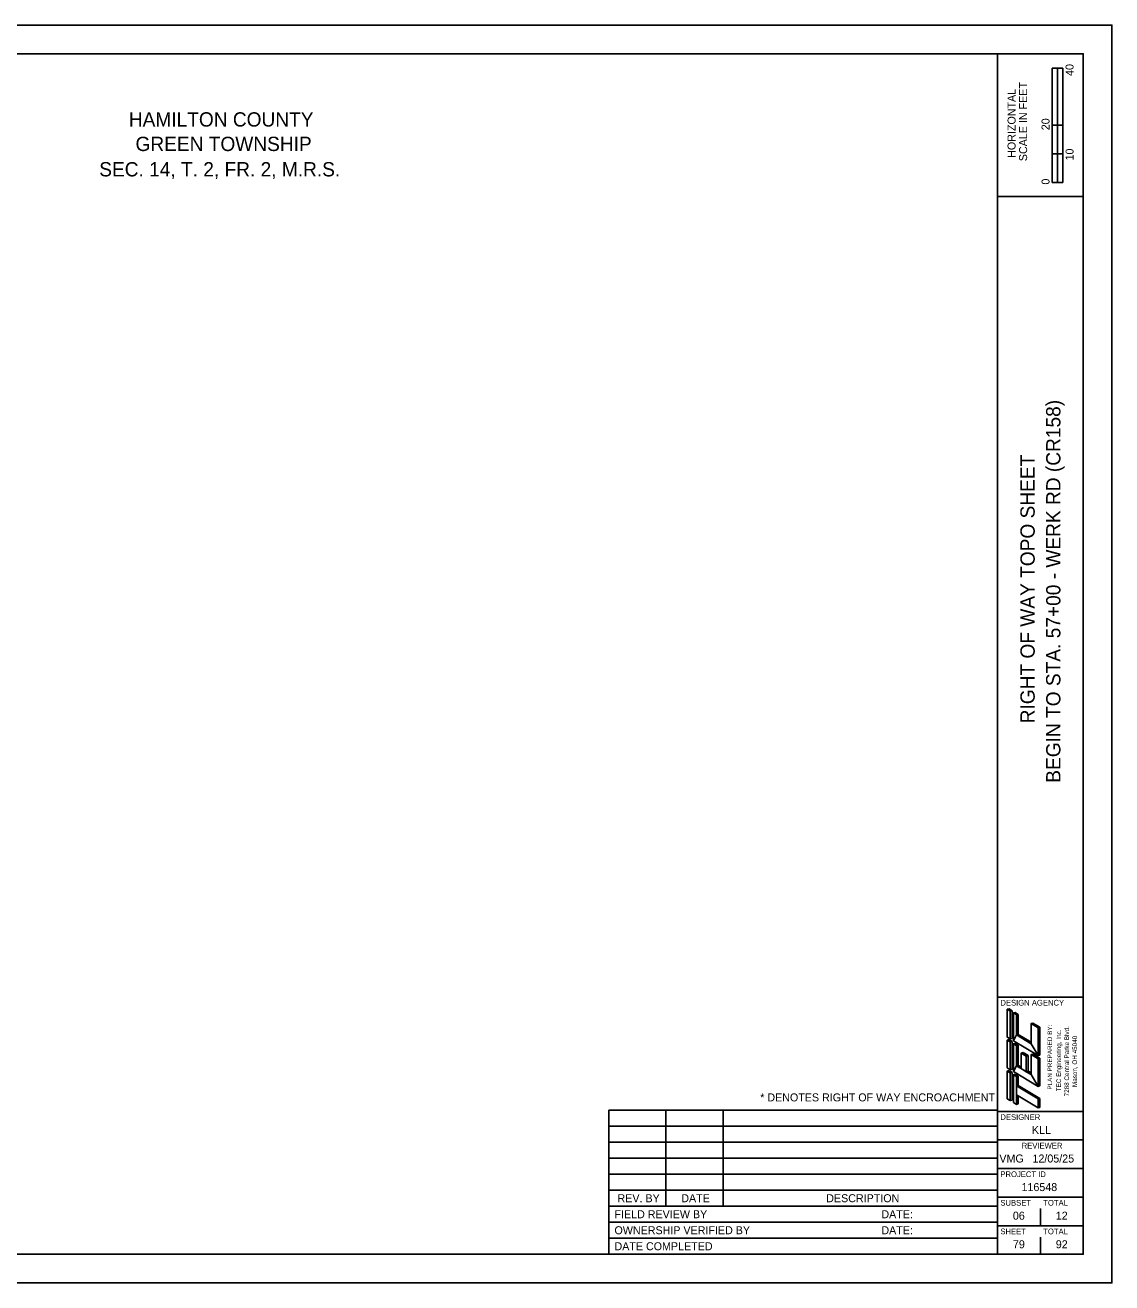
# Model space of a CAD drawing. Extents: x -4 to 34, y 0 to 23.7.
# Drawn here: x 14.98 to 34, y 0 to 22 of the extents above; entities that cross this region are included whole.
import ezdxf

# ---------------------------------------------------------------- set-up
doc = ezdxf.new("R2010")
doc.units = 0
for name, color, linetype in [('_CIVIL_CONSTRUCTION', 7, 'Continuous'), ('Default', 7, 'Continuous'), ('SC_Scratch1', 7, 'Continuous'), ('SG_P_Controllers', 7, 'Continuous'), ('SG_P_Detection', 7, 'Continuous'), ('SG_P_Heads', 7, 'Continuous')]:
    doc.layers.add(name, color=color, linetype=linetype)

msp = doc.modelspace()

# ---------------------------------------------------------------- linework, layer by layer
at = {"layer": '_CIVIL_CONSTRUCTION'}
for p, q in [((32.957, 19.25), (32.957, 21.25)), ((33.144, 21.25), (32.957, 21.25)), ((32.957, 20.25), (32.957, 21.25)), ((32.957, 21.25), (33.05, 21.25)), ((33.05, 21.25), (33.051, 21.25)), ((33.051, 21.25), (33.051, 20.25)), ((33.144, 21.25), (33.144, 19.25)), ((33.051, 20.25), (32.957, 20.25)), ((33.143, 20.25), (33.05, 20.25)), ((33.05, 20.25), (33.05, 19.75)), ((33.143, 19.75), (33.143, 20.25)), ((33.05, 19.75), (32.957, 19.75)), ((32.957, 19.75), (32.957, 19.25)), ((33.05, 19.25), (33.05, 19.75)), ((33.05, 19.75), (33.143, 19.75)), ((33.144, 19.25), (32.957, 19.25)), ((32.957, 19.25), (33.05, 19.25)), ((32.75, 4), (32.75, 4)), ((32.75, 1), (32.75, 1.3)), ((32.375, 0.675), (32.375, 0.675)), ((32.75, 0.5), (32.75, 0.8))]:
    msp.add_line(p, q, dxfattribs=at)
at = {"layer": 'SC_Scratch1'}
for p, q in [((32.169, 4.785), (32.201, 4.794)), ((32.169, 4.299), (32.169, 4.785)), ((32.223, 4.753), (32.169, 4.785)), ((32.255, 4.761), (32.201, 4.794)), ((32.223, 4.753), (32.255, 4.761)), ((32.223, 4.267), (32.223, 4.753)), ((32.255, 4.275), (32.255, 4.761)), ((32.277, 4.721), (32.309, 4.729)), ((32.331, 4.688), (32.277, 4.721)), ((32.277, 4.235), (32.277, 4.721)), ((32.309, 4.729), (32.363, 4.696)), ((32.331, 4.688), (32.363, 4.696)), ((32.331, 4.337), (32.331, 4.688)), ((32.363, 4.696), (32.363, 4.345)), ((32.587, 4.534), (32.62, 4.542)), ((32.587, 4.183), (32.587, 4.534)), ((32.709, 4.461), (32.587, 4.534)), ((32.62, 4.542), (32.741, 4.47)), ((32.709, 4.461), (32.741, 4.47)), ((32.709, 3.975), (32.709, 4.461)), ((32.741, 4.47), (32.741, 3.984)), ((32.223, 4.267), (32.169, 4.299)), ((32.169, 4.245), (32.201, 4.254)), ((32.169, 3.759), (32.169, 4.245)), ((32.223, 4.213), (32.169, 4.245)), ((32.255, 4.222), (32.201, 4.254)), ((32.223, 4.267), (32.255, 4.275)), ((32.223, 4.213), (32.255, 4.222)), ((32.223, 3.727), (32.223, 4.213)), ((32.255, 3.736), (32.255, 4.222)), ((32.709, 3.975), (32.277, 4.235)), ((32.277, 4.181), (32.309, 4.189)), ((32.277, 3.695), (32.277, 4.181)), ((32.331, 4.148), (32.277, 4.181)), ((32.309, 4.189), (32.363, 4.156)), ((32.331, 4.337), (32.363, 4.345)), ((32.587, 4.183), (32.331, 4.337)), ((32.363, 4.345), (32.587, 4.211)), ((32.331, 4.148), (32.363, 4.156)), ((32.331, 3.797), (32.331, 4.148)), ((32.363, 4.156), (32.363, 3.805)), ((32.415, 4.019), (32.448, 4.027)), ((32.415, 4.019), (32.415, 3.747)), ((32.415, 4.019), (32.503, 3.966)), ((32.448, 4.027), (32.535, 3.974)), ((32.503, 3.966), (32.535, 3.974)), ((32.503, 3.966), (32.503, 3.694)), ((32.535, 3.974), (32.535, 3.702)), ((32.587, 3.994), (32.62, 4.002)), ((32.587, 3.643), (32.587, 3.994)), ((32.709, 3.921), (32.587, 3.994)), ((32.62, 4.002), (32.741, 3.93)), ((32.709, 3.975), (32.741, 3.984)), ((32.223, 3.727), (32.169, 3.759)), ((32.331, 3.797), (32.363, 3.805)), ((32.415, 3.747), (32.331, 3.797)), ((32.363, 3.805), (32.415, 3.774)), ((32.709, 3.921), (32.741, 3.93)), ((32.709, 3.435), (32.709, 3.921)), ((32.741, 3.93), (32.741, 3.444)), ((32.169, 3.705), (32.201, 3.715)), ((32.169, 3.219), (32.169, 3.705)), ((32.223, 3.673), (32.169, 3.705)), ((32.255, 3.681), (32.201, 3.715)), ((32.222, 3.673), (32.255, 3.681)), ((32.223, 3.727), (32.255, 3.736)), ((32.223, 3.187), (32.223, 3.673)), ((32.255, 3.195), (32.255, 3.681)), ((32.709, 3.435), (32.277, 3.695)), ((32.277, 3.641), (32.309, 3.651)), ((32.331, 3.608), (32.277, 3.641)), ((32.277, 3.155), (32.277, 3.641)), ((32.309, 3.651), (32.363, 3.616)), ((32.331, 3.608), (32.363, 3.616)), ((32.331, 3.444), (32.331, 3.608)), ((32.363, 3.616), (32.363, 3.452)), ((32.503, 3.694), (32.535, 3.702)), ((32.587, 3.643), (32.503, 3.694)), ((32.535, 3.702), (32.587, 3.671)), ((32.331, 3.444), (32.363, 3.452)), ((32.331, 3.444), (32.709, 3.217)), ((32.363, 3.452), (32.741, 3.225)), ((32.709, 3.435), (32.741, 3.444)), ((32.223, 3.187), (32.169, 3.219)), ((32.223, 3.187), (32.255, 3.195)), ((32.331, 3.122), (32.277, 3.155)), ((32.331, 3.287), (32.709, 3.06)), ((32.331, 3.122), (32.331, 3.287)), ((32.331, 3.122), (32.363, 3.13)), ((32.363, 3.13), (32.363, 3.267)), ((32.709, 3.217), (32.741, 3.225)), ((32.709, 3.06), (32.709, 3.217)), ((32.741, 3.225), (32.741, 3.068)), ((25.197, 3.02), (25.197, 0.5)), ((25.197, 3.02), (32, 3.02)), ((26.197, 3.02), (26.197, 1.34)), ((27.197, 3.02), (27.197, 1.34)), ((32.709, 3.06), (32.741, 3.068)), ((25.197, 2.74), (32, 2.74)), ((25.197, 2.46), (32, 2.46)), ((25.197, 2.18), (32, 2.18)), ((25.197, 1.9), (32, 1.9)), ((25.197, 1.62), (32, 1.62)), ((25.197, 1.34), (32, 1.34)), ((25.197, 1.06), (32, 1.06)), ((25.197, 0.78), (32, 0.78)), ((32, 0.5), (32, 0.5))]:
    msp.add_line(p, q, dxfattribs=at)
for points in [[(32.169, 4.299), (32.223, 4.267), (32.223, 4.753), (32.169, 4.785)], [(32.277, 4.235), (32.331, 4.337), (32.331, 4.688), (32.277, 4.721)], [(32.709, 3.975), (32.587, 4.183), (32.587, 4.534), (32.709, 4.461)], [(32.169, 3.759), (32.223, 3.727), (32.223, 4.213), (32.169, 4.245)], [(32.277, 4.235), (32.331, 4.337), (32.587, 4.183), (32.709, 3.975)], [(32.277, 3.695), (32.331, 3.797), (32.331, 4.148), (32.277, 4.181)], [(32.415, 3.747), (32.415, 4.019), (32.503, 3.966), (32.503, 3.694)], [(32.709, 3.435), (32.587, 3.643), (32.587, 3.994), (32.709, 3.921)], [(32.277, 3.695), (32.331, 3.797), (32.587, 3.643), (32.709, 3.435)], [(32.169, 3.219), (32.223, 3.187), (32.223, 3.673), (32.169, 3.705)], [(32.277, 3.155), (32.331, 3.122), (32.331, 3.608), (32.277, 3.641)], [(32.331, 3.287), (32.331, 3.444), (32.709, 3.217), (32.709, 3.06)]]:
    msp.add_lwpolyline(points, close=True, dxfattribs=at)
at = {"layer": 'SG_P_Detection'}
msp.add_lwpolyline([(0, 0), (34, 0), (34, 22), (0, 22)], close=True, dxfattribs=at)
at = {"layer": 'SG_P_Heads'}
for p, q in [((32, 0.5), (32, 21.5)), ((32, 19), (33.5, 19)), ((32, 5), (33.5, 5)), ((32, 3), (33.5, 3)), ((32, 2.5), (33.5, 2.5)), ((32, 2), (33.5, 2)), ((32, 1.5), (33.5, 1.5)), ((32, 1), (33.5, 1))]:
    msp.add_line(p, q, dxfattribs=at)
msp.add_lwpolyline([(1.5, 21.5), (33.5, 21.5), (33.5, 0.5), (1.5, 0.5)], close=True, dxfattribs=at)

# ---------------------------------------------------------------- texts
at = {"layer": '_CIVIL_CONSTRUCTION'}
for s, height, p in [('40', 0.14, (33.33, 21.112)), ('SCALE IN FEET', 0.14, (32.517, 19.621)), ('HORIZONTAL', 0.14, (32.315, 19.679)), ('20', 0.14, (32.91, 20.162)), ('10', 0.14, (33.33, 19.633)), ('0', 0.14, (32.91, 19.211)), ('BEGIN TO STA. 57+00 - WERK RD (CR158)', 0.25, (33.1, 8.748)), ('RIGHT OF WAY TOPO SHEET', 0.25, (32.65, 9.787))]:
    msp.add_text(s, height=height, rotation=90, dxfattribs=at).set_placement(p)
for s, height, p in [('DESIGN AGENCY', 0.1, (32.05, 4.85)), ('DESIGNER', 0.1, (32.05, 2.85)), ('KLL', 0.14, (32.601, 2.605)), ('REVIEWER', 0.1, (32.422, 2.35)), ('VMG', 0.14, (32.032, 2.105)), ('12/05/25', 0.14, (32.611, 2.105)), ('PROJECT ID', 0.1, (32.05, 1.85)), ('116548', 0.14, (32.419, 1.605)), ('SUBSET', 0.1, (32.05, 1.35)), ('TOTAL', 0.1, (32.8, 1.35)), ('06', 0.14, (32.268, 1.105)), ('12', 0.14, (33.019, 1.105)), ('SHEET', 0.1, (32.05, 0.85)), ('TOTAL', 0.1, (32.8, 0.85)), ('79', 0.14, (32.269, 0.605)), ('92', 0.14, (33.019, 0.605))]:
    msp.add_text(s, height=height, dxfattribs=at).set_placement(p)
at = {"layer": 'Default'}
for s, p in [('PLAN PREPARED BY:', (32.954, 3.38)), ('7288 Central Parke Blvd.', (33.25, 3.262)), ('TEC Engineering, Inc.', (33.11, 3.351)), ('Mason, OH 45040', (33.39, 3.425))]:
    msp.add_text(s, height=0.08, rotation=90, dxfattribs=at).set_placement(p)
at = {"layer": 'SC_Scratch1'}
for s, p in [('* DENOTES RIGHT OF WAY ENCROACHMENT', (27.847, 3.174)), ('REV. BY', (25.35, 1.41)), ('DATE', (26.466, 1.41)), ('DESCRIPTION', (29.002, 1.41)), ('FIELD REVIEW BY', (25.297, 1.13)), ('DATE:', (29.967, 1.13)), ('OWNERSHIP VERIFIED BY', (25.297, 0.85)), ('DATE:', (29.967, 0.85)), ('DATE COMPLETED', (25.297, 0.57))]:
    msp.add_text(s, height=0.14, dxfattribs=at).set_placement(p)
at = {"layer": 'SG_P_Controllers'}
for s, p in [('HAMILTON COUNTY', (16.799, 20.226)), ('   GREEN TOWNSHIP', (16.637, 19.798)), ('SEC. 14, T. 2, FR. 2, M.R.S.', (16.281, 19.354))]:
    msp.add_text(s, height=0.25, dxfattribs=at).set_placement(p)

doc.saveas('drawing.dxf')
